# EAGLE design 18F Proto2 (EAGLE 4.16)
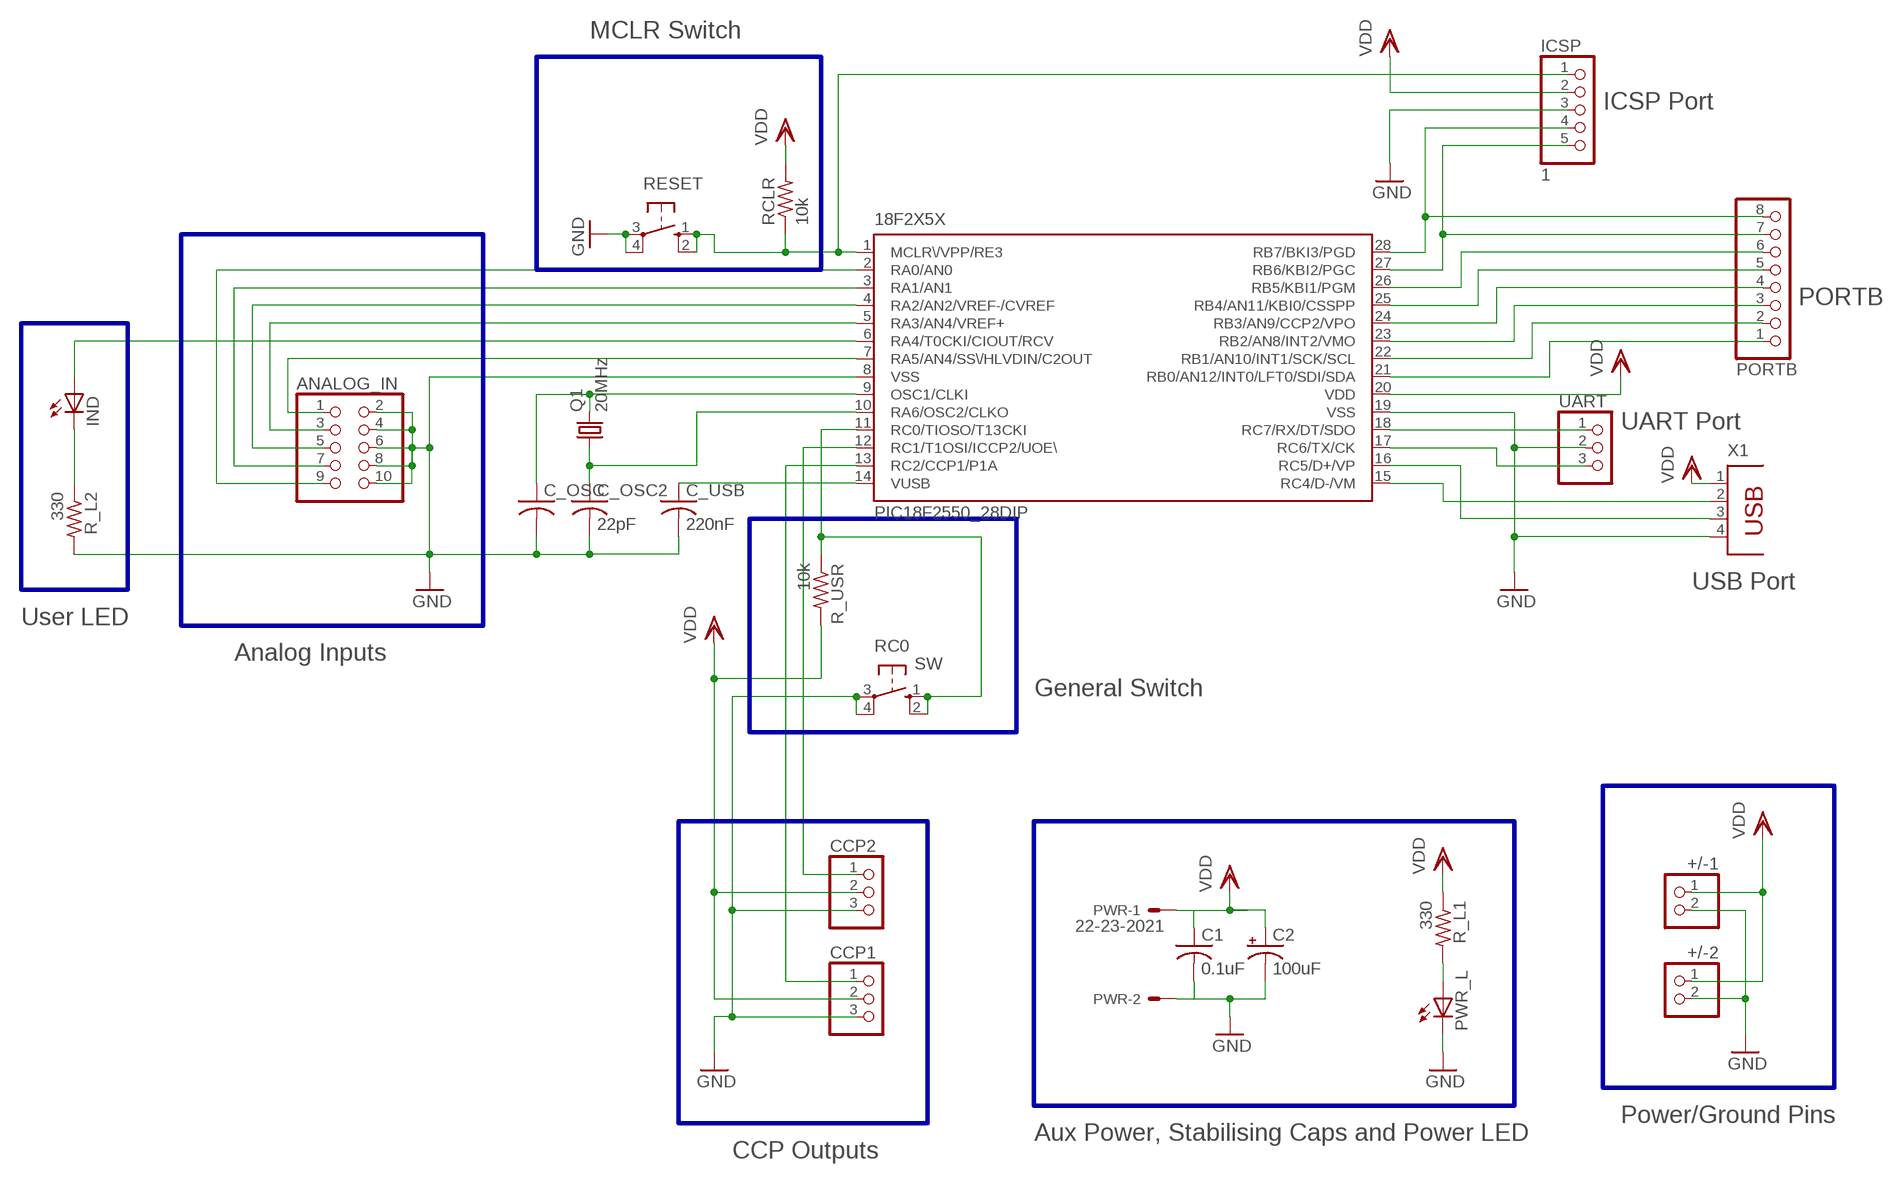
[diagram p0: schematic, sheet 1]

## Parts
18F2X5X  PIC18F2550_28DIP  [DIL28-3]
+/-1  PINHD-1X2  [1X02]
+/-2  PINHD-1X2  [1X02]
ANALOG_IN  PINHD-2X5  [2X05]
C1  0.1uF  C-US050-025X075  [C050-025X075]
C2  100uF  CPOL-USE2.5-6  [E2,5-6]
C_OSC  C-US025-025X050  [C025-025X050]
C_OSC2  22pF  C-US025-025X050  [C025-025X050]
C_USB  220nF  C-US050-025X075  [C050-025X075]
CCP1  PINHD-1X3  [1X03]
CCP2  PINHD-1X3  [1X03]
ICSP  1  PINHD-1X5  [1X05]
IND  LED3MM  [LED3MM]
PORTB  PINHD-1X8  [1X08]
PWR  22-23-2021  [22-23-2021]
PWR_L  LED3MM  [LED3MM]
Q1  20MHz  CRYSTALHC49S  [HC49/S]
R_L1  330  R-US_0204/7  [0204/7]
R_L2  330  R-US_0207/10  [0207/10]
R_USR  10k  R-US_0204/7  [0204/7]
RC0  SW  10-XX  [B3F-10XX]
RCLR  10k  R-US_0204/7  [0204/7]
RESET  10-XX  [B3F-10XX]
UART  PINHD-1X3  [1X03]
X1  PN61729  [PN61729]

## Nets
D+: 18F2X5X.16(RC5/D+/VP) X1.3
D-: 18F2X5X.15(RC4/D-/VM) X1.2
GND: 18F2X5X.8(VSS) 18F2X5X.19(VSS) +/-1.2 +/-2.2 ANALOG_IN.2 ANALOG_IN.4 ANALOG_IN.6 ANALOG_IN.8 ANALOG_IN.10 C1.2 C2.- C_OSC2.2 C_OSC.2 C_USB.2 CCP1.3 CCP2.3 ICSP.3 PWR.2 PWR_L.K(C) R_L2.2 RC0.3(P) RC0.4(P1) RESET.3(P) RESET.4(P1) UART.2 X1.4
MCLR: 18F2X5X.1(MCLR\/VPP/RE3) ICSP.1 RCLR.1 RESET.1(S) RESET.2(S1)
N$4: 18F2X5X.10(RA6/OSC2/CLKO) C_OSC2.1 Q1.1
N$5: PWR_L.A R_L1.2
N$7: 18F2X5X.9(OSC1/CLKI) C_OSC.1 Q1.2
N$9: 18F2X5X.14(VUSB) C_USB.1
N$12: 18F2X5X.2(RA0/AN0) ANALOG_IN.9
N$13: 18F2X5X.3(RA1/AN1) ANALOG_IN.7
N$14: 18F2X5X.4(RA2/AN2/VREF-/CVREF) ANALOG_IN.5
N$15: 18F2X5X.5(RA3/AN4/VREF+) ANALOG_IN.3
N$16: 18F2X5X.6(RA4/T0CKI/CIOUT/RCV) IND.A
N$17: 18F2X5X.7(RA5/AN4/SS\/HLVDIN/C2OUT) ANALOG_IN.1
N$18: IND.K(C) R_L2.1
N$19: 18F2X5X.11(RC0/TIOSO/T13CKI) R_USR.1 RC0.1(S) RC0.2(S1)
N$20: 18F2X5X.12(RC1/T1OSI/ICCP2/UOE\) CCP2.1
N$21: 18F2X5X.13(RC2/CCP1/P1A) CCP1.1
N$22: 18F2X5X.21(RB0/AN12/INT0/LFT0/SDI/SDA) PORTB.1
N$23: 18F2X5X.22(RB1/AN10/INT1/SCK/SCL) PORTB.2
N$24: 18F2X5X.23(RB2/AN8/INT2/VMO) PORTB.3
N$25: 18F2X5X.24(RB3/AN9/CCP2/VPO) PORTB.4
N$26: 18F2X5X.25(RB4/AN11/KBI0/CSSPP) PORTB.5
N$27: 18F2X5X.26(RB5/KBI1/PGM) PORTB.6
PGC: 18F2X5X.27(RB6/KBI2/PGC) ICSP.5 PORTB.7
PGD: 18F2X5X.28(RB7/BKI3/PGD) ICSP.4 PORTB.8
RX: 18F2X5X.18(RC7/RX/DT/SDO) UART.1
TX: 18F2X5X.17(RC6/TX/CK) UART.3
VDD: 18F2X5X.20(VDD) +/-1.1 +/-2.1 C1.1 C2.+ CCP1.2 CCP2.2 ICSP.2 PWR.1 R_L1.1 R_USR.2 RCLR.2 X1.1

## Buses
B$1
B$2
B$3
B$4
B$5
B$6
B$7

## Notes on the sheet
- MCLR Switch
- ICSP Port
- PORTB
- UART Port
- USB Port
- User LED
- Analog Inputs
- General Switch
- Power/Ground Pins
- Aux Power, Stabilising Caps and Power LED
- CCP Outputs

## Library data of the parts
18F2X5X = microchip:PIC18F2*_28: USB Microcontrollers with nanoWatt Technology High-Performance, Enhanced Flash, 28/40/44-Pin, Source: http://ww1.microchip.com/downloads/en/devicedoc/39632c.pdf
+/-1 +/-2 = pinhead:PINHD-1X2: PIN HEADER
ANALOG_IN = pinhead:PINHD-2X5: PIN HEADER
C1 C_OSC C_OSC2 C_USB = rcl:C-US: CAPACITOR, American symbol
C2 = rcl:CPOL-US: POLARIZED CAPACITOR, American symbol
CCP1 CCP2 UART = pinhead:PINHD-1X3: PIN HEADER
ICSP = pinhead:PINHD-1X5: PIN HEADER
IND PWR_L = led:LED: LED
PORTB = pinhead:PINHD-1X8: PIN HEADER
PWR = con-molex:22-23-2021: .100" (2.54mm) Center Header - 2 Pin
Q1 = crystal:CRYSTAL: CRYSTAL
R_L1 R_L2 R_USR RCLR = rcl:R-US_: RESISTOR, American symbol
RC0 RESET = switch-omron:10-XX: OMRON SWITCH
X1 = con-berg:PN61729: BERG USB connector

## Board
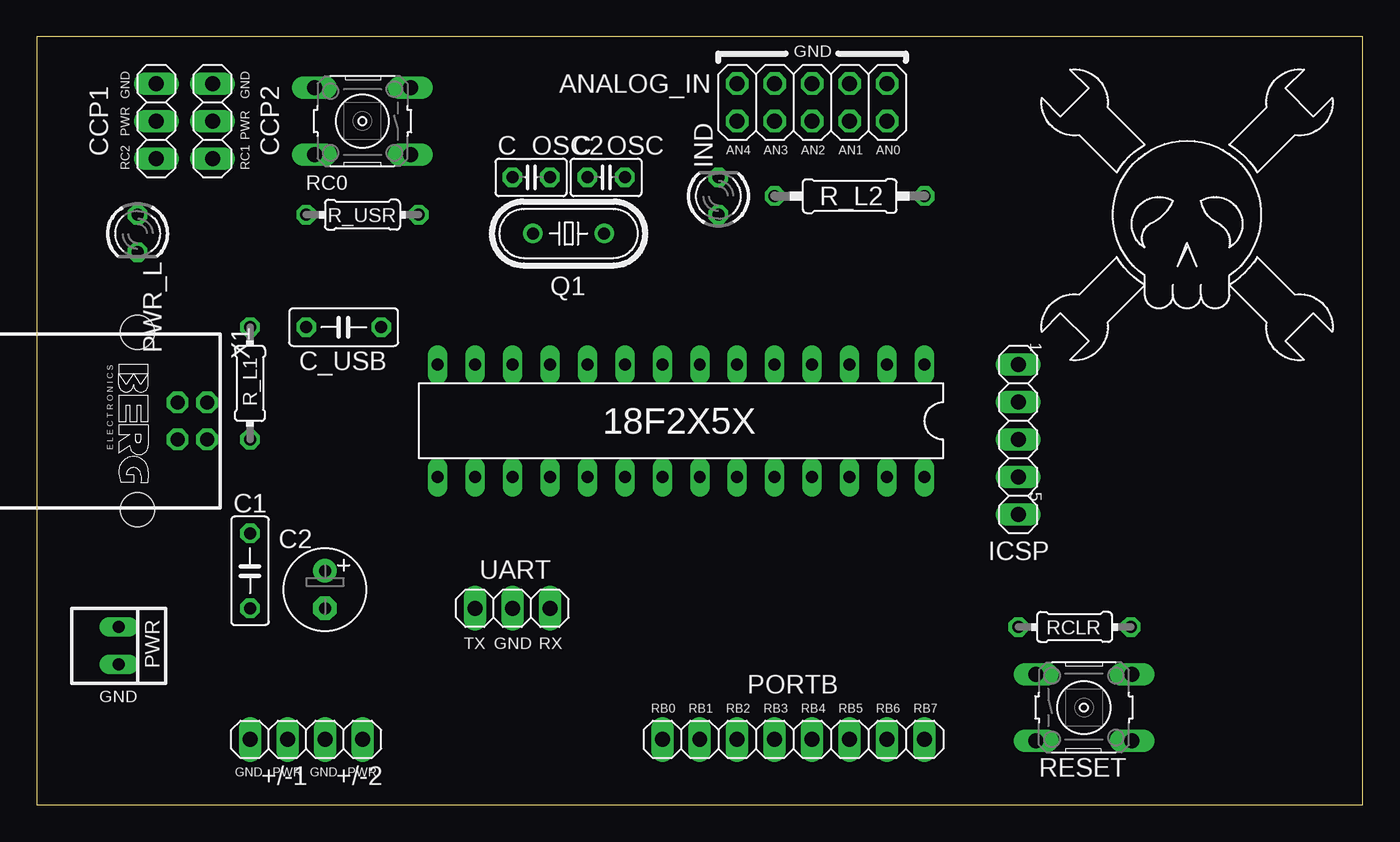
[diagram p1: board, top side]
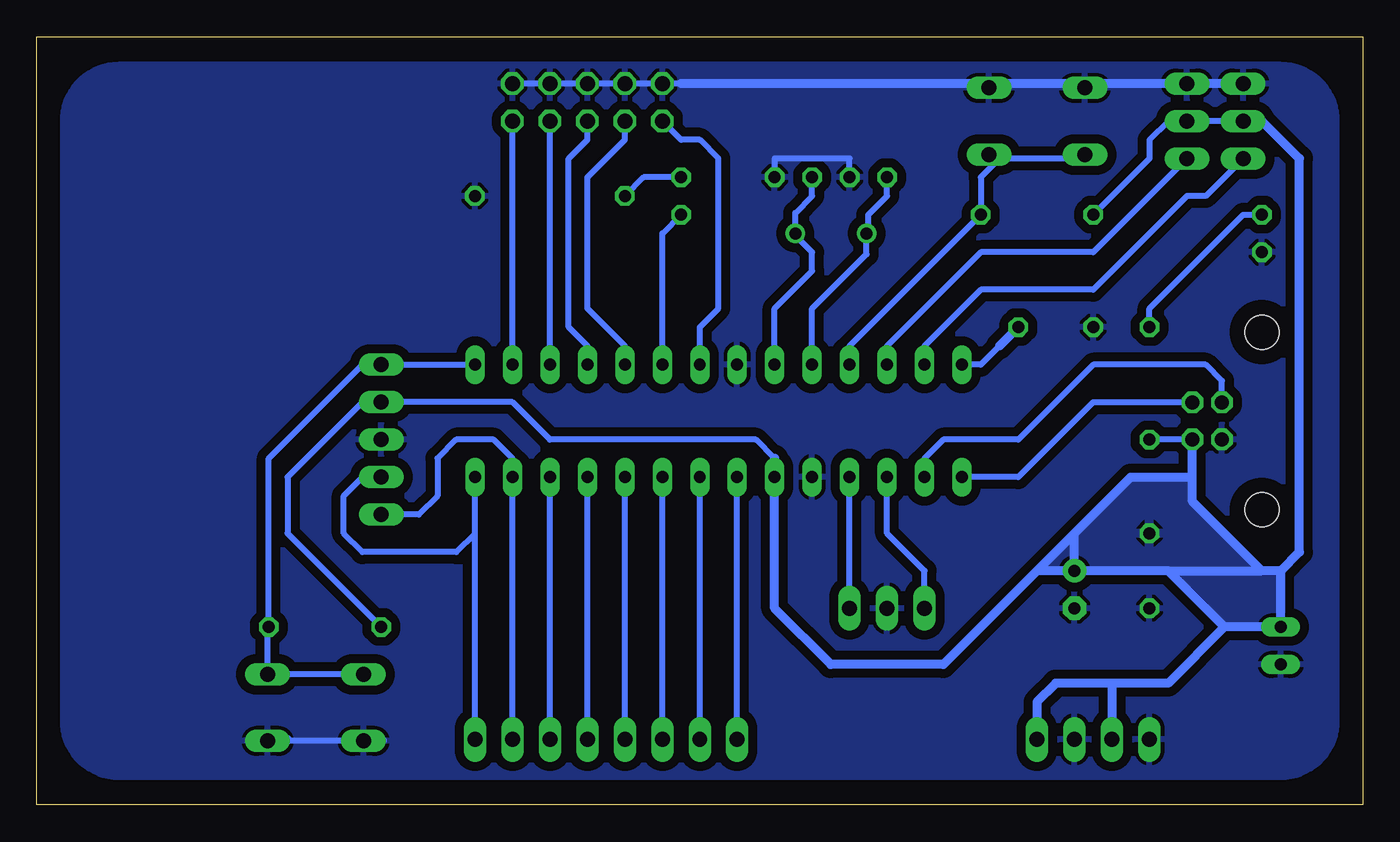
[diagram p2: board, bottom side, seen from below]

Size 89.84 x 52.06 mm. Coordinates in mm from the lower left corner, seen from the top.
Outline: 0,0 89.84,0 89.84,52.06 0,52.06 0,0
Copper layers (1*16): Top 0.035mm / dielectric 1.5mm / Bottom 0.035mm
Design rules "default": minimum track width 10mil, minimum drill 24mil, track to track 8mil, track to pad 8mil, pad to pad 8mil, via to via 8mil, smd to smd 8mil, copper to edge 40mil, drill to drill 8mil, minimum pad ring 10mil, minimum via ring 8mil, stop-mask expansion 4mil, vias tented up to drill 0mil, thermal gap 10mil

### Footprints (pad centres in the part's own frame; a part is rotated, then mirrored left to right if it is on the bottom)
DIL28-3 = drill 0.813 long: 1 -16.51,-3.81; 2 -13.97,-3.81; 3 -11.43,-3.81; 4 -8.89,-3.81; 5 -6.35,-3.81; 6 -3.81,-3.81; 7 -1.27,-3.81; 8 1.27,-3.81; 9 3.81,-3.81; 10 6.35,-3.81; 11 8.89,-3.81; 12 11.43,-3.81; 13 13.97,-3.81; 14 16.51,-3.81; 15 16.51,3.81; 16 13.97,3.81; 17 11.43,3.81; 18 8.89,3.81; 19 6.35,3.81; 20 3.81,3.81; 21 1.27,3.81; 22 -1.27,3.81; 23 -3.81,3.81; 24 -6.35,3.81; 25 -8.89,3.81; 26 -11.43,3.81; 27 -13.97,3.81; 28 -16.51,3.81
1X02 = drill 1.016 long: 1 -1.27,0; 2 1.27,0
2X05 = drill 1.016 octagon: 1 -5.08,-1.27; 2 -5.08,1.27; 3 -2.54,-1.27; 4 -2.54,1.27; 5 0,-1.27; 6 0,1.27; 7 2.54,-1.27; 8 2.54,1.27; 9 5.08,-1.27; 10 5.08,1.27
C050-025X075 = drill 0.813 octagon: 1 -2.54,0; 2 2.54,0
E2,5-6 = drill 0.813 pad 1.6 round: + -1.27,0 | drill 0.813 pad 1.6 octagon: - 1.27,0
C025-025X050 = drill 0.813 octagon: 1 -1.27,0; 2 1.27,0
1X03 = drill 1.016 long: 1 -2.54,0; 2 0,0; 3 2.54,0
1X05 = drill 1.016 long: 1 -5.08,0; 2 -2.54,0; 3 0,0; 4 2.54,0; 5 5.08,0
LED3MM = drill 0.813 octagon: A -1.27,0; K 1.27,0
1X08 = drill 1.016 long: 1 -8.89,0; 2 -6.35,0; 3 -3.81,0; 4 -1.27,0; 5 1.27,0; 6 3.81,0; 7 6.35,0; 8 8.89,0
22-23-2021 = drill 0.813 long: 1 -1.27,0; 2 1.27,0
HC49/S = drill 0.813 round: 1 -2.413,0; 2 2.413,0
0204/7 = drill 0.813 octagon: 1 -3.81,0; 2 3.81,0
0207/10 = drill 0.813 octagon: 1 -5.08,0; 2 5.08,0
B3F-10XX = drill 1.016 long: 1 -3.251,2.261; 2 3.251,2.261; 3 -3.251,-2.261; 4 3.251,-2.261
PN61729 = drill 0.95 octagon: 1 1.25,4.71; 2 -1.25,4.71; 3 -1.25,2.71; 4 1.25,2.71 | hole 2.3: -6.02,0; 6.02,0

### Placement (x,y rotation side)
18F2X5X  43.65,26.03 180 top
+/-1  15.71,4.44 180 top
+/-2  20.79,4.44 180 top
ANALOG_IN  52.54,47.62 0 top
C1  14.44,15.87 270 top
C2  19.52,14.6 270 top
C_OSC  38.57,42.54 0 top
C_OSC2  33.49,42.54 0 top
C_USB  20.79,32.38 180 top
CCP1  8.09,46.35 90 top
CCP2  11.9,46.35 90 top
ICSP  66.51,24.76 270 top
IND  46.19,41.27 90 top
PORTB  51.27,4.44 0 top
PWR  5.55,10.79 270 top
PWR_L  6.82,38.73 270 top
Q1  36.03,38.73 0 top
R_L1  14.44,28.57 90 top
R_L2  55.08,41.27 0 top
R_USR  22.06,40 180 top
RC0  22.06,46.35 180 top
RCLR  70.32,12.06 180 top
RESET  70.95,6.6 0 top
U$1  [HACKADAY_S]  77.94,40 0 top
UART  32.22,13.33 180 top
X1  6.82,26.03 270 top

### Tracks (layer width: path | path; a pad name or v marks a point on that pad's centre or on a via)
D+
  Bottom 0.406: X1.3 9.53,28.74 10.63,29.84 18.25,29.84 23.33,24.76 28.41,24.76 29.68,23.49 18F2X5X.16
D-
  Bottom 0.406: 18F2X5X.15 23.33,22.22 18.25,27.3 18.23,27.28 X1.2
GND
  Bottom 0.406: C_OSC2.2 34.76,43.81 39.84,43.81 C_OSC.2 | 72.94,4.36 RESET.4 | RESET.3 72.76,4.34 72.86,4.44 | ANALOG_IN.10 ANALOG_IN.8 ANALOG_IN.6 ANALOG_IN.4 ANALOG_IN.2 46.19,48.89
  Bottom 0.61: RC0.4 19.24,48.61 19.52,48.89 | 19.52,48.89 24.6,48.89 | CCP1.3 CCP2.3 19.52,48.89 | RC0.3 24.88,48.61 24.6,48.89 | 24.6,48.89 46.19,48.89 | 72.86,4.44 72.94,4.36 | 66.51,4.44 66.43,4.36 RESET.3
  pour Bottom (isolate 0.61): 1.74,46.35 arc-90 5.55,50.16 84.29,50.16 arc-90 88.1,46.35 88.1,5.71 arc-90 84.29,1.9 5.55,1.9 arc-90 1.74,5.71
MCLR
  Bottom 0.406: RESET.1 RESET.2 74.21,11.98 RCLR.1 74.13,23.49 67.78,29.84 ICSP.1 18F2X5X.1
N$4
  Bottom 0.406: C_OSC2.1 32.22,41.27 33.49,40 33.49,38.73 Q1.1 33.62,37.33 37.3,33.65 18F2X5X.10
N$5
  Bottom 0.406: R_L1.2 14.44,33.65 8.09,40 PWR_L.A
N$7
  Bottom 0.406: C_OSC.1 37.3,41.27 38.44,40.13 Q1.2 38.57,38.73 37.3,37.46 37.3,36.19 39.84,33.65 18F2X5X.9
N$9
  Bottom 0.406: 24.6,31.11 25.87,29.84 18F2X5X.14
  Bottom 0.61: C_USB.1 24.6,31.11
N$12
  Bottom 0.406: 18F2X5X.2 ANALOG_IN.9
N$13
  Bottom 0.406: 18F2X5X.3 ANALOG_IN.7
N$14
  Bottom 0.406: ANALOG_IN.5 52.54,45.08 53.81,43.81 53.81,32.38 52.54,31.11 18F2X5X.4
N$15
  Bottom 0.406: ANALOG_IN.3 50,45.08 52.54,42.54 52.54,33.65 50,31.11 18F2X5X.5
N$16
  Bottom 0.406: IND.A 47.46,38.73 18F2X5X.6
N$17
  Bottom 0.406: ANALOG_IN.1 46.19,45.08 44.92,45.08 43.65,43.81 43.65,33.65 44.92,32.38 18F2X5X.7
N$18
  Bottom 0.406: IND.K 48.73,42.54 R_L2.1
N$19
  Bottom 0.406: RC0.2 19.24,44.09 19.52,43.81 24.6,43.81 | RC0.1 24.88,44.09 24.6,43.81 | 24.6,43.81 25.87,42.54 R_USR.1 34.76,31.11 18F2X5X.11
N$20
  Bottom 0.406: CCP2.1 18.25,37.46 25.87,37.46 32.22,31.11 18F2X5X.12
N$21
  Bottom 0.406: CCP1.1 10.63,41.27 11.9,41.27 18.25,34.92 25.87,34.92 29.68,31.11 18F2X5X.13
N$22
  Bottom 0.406: PORTB.1 18F2X5X.21
N$23
  Bottom 0.406: PORTB.2 18F2X5X.22
N$24
  Bottom 0.406: PORTB.3 18F2X5X.23
N$25
  Bottom 0.406: PORTB.4 18F2X5X.24
N$26
  Bottom 0.406: PORTB.5 18F2X5X.25
N$27
  Bottom 0.406: PORTB.6 18F2X5X.26
PGC
  Bottom 0.406: PORTB.7 18F2X5X.27 57.62,23.49 58.89,24.76 61.43,24.76 62.7,23.49 62.7,20.95 63.97,19.68 ICSP.5
PGD
  Bottom 0.406: PORTB.8 60.16,18.41 | 60.16,18.41 18F2X5X.28 | 60.16,18.41 61.43,17.14 67.78,17.14 69.05,18.41 69.05,20.95 67.78,22.22 ICSP.4
RX
  Bottom 0.406: UART.1 18F2X5X.18
TX
  Bottom 0.406: UART.3 29.68,15.87 32.22,18.41 18F2X5X.17
VDD
  Bottom 0.406: R_USR.2 14.44,43.81 14.44,45.08 13.17,46.35 CCP2.2 CCP1.2 | 39.84,23.49 41.11,24.76 55.08,24.76 57.62,27.3 ICSP.2 67.78,27.3 72.86,22.22 72.86,18.41 RCLR.2 | X1.1 14.42,24.78 R_L1.1
  Bottom 0.61: 5.55,15.87 4.28,17.14 4.28,43.81 6.82,46.35 CCP1.2 | 16.98,8.25 20.79,8.25 22.06,6.98 +/-2.1 | 16.98,8.25 +/-1.1 | 5.55,15.87 PWR.1 9.36,12.06 | 39.84,23.49 18F2X5X.20 39.84,13.33 36.03,9.52 28.41,9.52 22.06,15.87 | 16.98,8.25 13.17,8.25 9.36,12.06 | C2.+ 19.52,18.41 | C2.+ 22.06,15.87 | 5.55,15.87 6.82,15.87 | 19.52,18.41 22.06,15.87 | 19.52,18.41 15.71,22.22 11.9,22.22 | 13.17,15.87 6.82,15.87 | 13.17,15.87 C2.+ | X1.1 11.53,20.58 6.82,15.87 | 9.36,12.06 13.17,15.87
  pour Bottom: 5.55,12.06 9.36,12.06 13.17,15.87 22.06,15.87 15.71,22.22 11.9,22.22 11.9,20.95 6.82,15.87 5.55,15.87

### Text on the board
tNames: GND | GND | GND | PWR | PWR | AN4 | AN3 | AN2 | AN1 | AN0 | RC2 | RC1 | 1 | 5 | TX | GND | RX | GND | RB0 | RB1 | RB2 | RB3 | RB4 | RB5 | RB6 | RB7 | GND | PWR | GND | PWR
